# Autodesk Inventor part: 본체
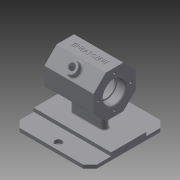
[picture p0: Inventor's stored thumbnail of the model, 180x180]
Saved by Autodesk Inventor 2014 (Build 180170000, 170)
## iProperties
Created: 2018-06
Part Number: 본체
Material: Generic
Document SubType Name: Modeling
Designer: kh
Density: 1 g/cm^3
Appearance: Default
Author: kh
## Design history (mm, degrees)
sketch "Sketch1"
  geometry: L1 (-55, -55)-(55, -55); L2 (55, -55)-(55, 55); L3 (55, 55)-(-55, 55); L4 (-55, 55)-(-55, -55); L5 (-55, -55)-(55, 55); L6 (55, -55)-(-55, 55); 1 further point
  constraints: 12 end point, 2 midpoint, 2 parallel, 1 horizontal, 1 perpendicular
  dimensions: "d0" = 110 distance of L3.end L2.end; "d1" = 110 distance of L3.end L1.start
extrude "Extrusion1" new body sketch "Sketch1" distance "d2" = 5; taper "d3" = 0 deg
chamfer "Chamfer1" distance "d4" = 10; stored, may be unused: second distance "d5" = 2, angle "d6" = 45 deg
sketch "Sketch2"
  geometry: L1 (-45, -55)-(-55, -45) reference; L2 (-45, -55)-(45, -55) reference; L3 (55, -45)-(45, -55) reference; L4 (55, -45)-(55, 45) reference; L5 (45, 55)-(55, 45) reference; L6 (45, 55)-(-45, 55) reference; L7 (-55, 45)-(-45, 55) reference; L8 (-55, 45)-(-55, -45) reference; L9 (-55, 25)-(55, 25); L10 (55, 25)-(55, -25); L11 (55, -25)-(-55, -25); L12 (-55, -25)-(-55, 25); L13 (0, 0)-(0, 55)
  constraints: 10 end point, 2 parallel, 2 point on line, 1 horizontal, 1 midpoint, 1 perpendicular
  dimensions: "d7" = 30 distance between parallel lines of L11 L2; "d8" = 30 distance between parallel lines of L9 L6
extrude "Extrusion2" join sketch "Sketch2" distance "d9" = 5; taper "d10" = 0 deg
workplane "Work Plane1"
sketch "Sketch3"
  geometry: L1 (35, 62)-(-35, 62); L2 (-35, 92)-(35, 92); L3 (-35, 92)-(-35, 62); L4 (35, 92)-(35, 62); 1 further point
  constraints: 8 end point, 2 parallel, 1 perpendicular
  dimensions: "d13" = 70 distance of L2.start L2.end
revolve "Revolution1" sketch "Sketch3" stored, may be unused: angle "d15" = 90 deg
sketch "Sketch4"
  geometry: L1 (-55, -45)-(-45, -55) reference; L2 (-55, 45)-(-55, -45) reference; L3 (-45, 55)-(-55, 45) reference; L4 (45, 55)-(-45, 55) reference; L5 (55, 45)-(45, 55) reference; L6 (55, -45)-(55, 45) reference; L7 (45, -55)-(55, -45) reference; L8 (-45, -55)-(45, -55) reference; L9 (55, -25)-(-55, -25) reference; L10 (-19, 0)-(19, 0); L11 (-19, -5)-(19, -5); L12 (19, 5)-(-19, 5); A1 r 5 centre (-19, 0) between (-19, 5) and (-19, -5); A2 r 5 centre (19, 0) between (19, -5) and (19, 5); 2 further points
  constraints: 8 end point, 4 point on circle, 4 tangent, 2 centre point, 2 parallel, 1 coincident, 1 midpoint
  dimensions: "d16" = 38 distance of L10.start L10.end; "d17" = 10 diameter of A2
extrude "Extrusion3" join sketch "Sketch4" stored distance "d18" = 5; taper "d19" = 0 deg
sketch "Sketch5"
  geometry: L1 (35, -30)-(35, 30) reference; L2 (55, -45)-(55, -25) reference; L3 (-45, -55)-(45, -55) reference; L4 (0, -55)-(0, -25); L5 (-13.688, -45)-(25.666, -45); 2 further points
  constraints: 4 end point, 2 perpendicular, 2 point on line, 1 midpoint
  dimensions: "d20" = 10 distance between parallel lines of L5 L3
hole "Hole1" sketch "Sketch5" at (0, -45) diameter "d21" = 10; stored, may be unused: countersink angle "d25" = 90 deg, drill point angle "d27" = 118 deg; dims "d22" = 6, "d23" = 4, "d24" = 2, "d26" = 8
mirror "Mirror1"
sketch "Sketch6"
  geometry: L1 (30, -12.426)-(12.426, -30); L2 (12.426, -30)-(-12.426, -30); L3 (-12.426, -30)-(-30, -12.426); L4 (-30, -12.426)-(-30, 12.426); L5 (-30, 12.426)-(-12.426, 30); L6 (-12.426, 30)-(12.426, 30); L7 (12.426, 30)-(30, 12.426); L8 (30, 12.426)-(30, -12.426); L9 (0, 0)-(30, 0); 2 further points
  constraints: 18 end point, 1 coincident, 1 horizontal alignment, 1 midpoint, 1 perpendicular, 18 other
extrude "Extrusion4" join sketch "Sketch6" distance "d28" = 70; taper "d29" = 0 deg
sketch "Sketch7"
  geometry: L1 (-35, 49.574)-(-35, 74.426) reference; L2 (35, 49.574)-(35, 74.426) reference; L3 (-35, 62)-(35, 62); L4 (-23, 78)-(-23, 76); L5 (-23, 76)-(-19.455, 76); L6 (-19.455, 76)-(-19.455, 87); L7 (-19.455, 87)-(20.545, 87); L8 (20.545, 87)-(20.545, 76); L9 (20.545, 76)-(23, 76); L10 (-23, 78)-(-35, 78); L11 (23, 76)-(23, 78); L12 (23, 78)-(35, 78); L13 (-35, 78)-(-35, 62); L14 (35, 78)-(35, 62); 1 further point
  constraints: 24 end point, 3 perpendicular, 2 collinear, 2 midpoint, 2 parallel, 1 point on line
  dimensions: "d30" = 32 diameter of L10 L3; "d31" = 28 diameter of L5 L3; "d32" = 50 diameter of L7 L3; "d33" = 28 diameter of L9 L3; "d34" = 32 diameter of L12 L3; "d35" = 12 distance between parallel lines of L4 L13; "d37" = 12 distance of L11.end L12.end; "d38" = 40 distance between parallel lines of L8 L6
revolve "Revolution2" sketch "Sketch7" stored, may be unused: angle "d39" = 90 deg
sketch "Sketch8" dims "d40" = 46
  geometry: L1 (42.426, 42.426)-(60, 24.853) reference; L2 (17.574, 42.426)-(42.426, 42.426) reference; L3 (0, 24.853)-(17.574, 42.426) reference; L4 (0, 0)-(0, 24.853) reference; L5 (17.574, -17.574)-(0, 0) reference; L6 (42.426, -17.574)-(17.574, -17.574) reference; L7 (60, 0)-(42.426, -17.574) reference; L8 (60, 24.853)-(60, 0) reference; L9 (30, 12.426)-(60, 12.426); C1 r 14 at (30, 12.426) reference; C2 r 16 at (30, 12.426) reference; 3 further points
  constraints: 2 end point, 1 coincident, 1 horizontal alignment, 1 midpoint, 2 other
hole "Hole2" sketch "Sketch8" at (53, 12.426) diameter "d41" = 3.459; stored, may be unused: countersink angle "d45" = 90 deg, drill point angle "d47" = 118 deg; dims "d42" = 8, "d43" = 4, "d44" = 2, "d46" = 10
pattern_circular "Circular Pattern1" dims angle "d49" = 360 deg
mirror "Mirror2"
sketch "Sketch9"
  geometry: L1 (10.113, 16.029)-(59.887, 16.029); L2 (59.887, 16.029)-(59.887, 8.824); L3 (59.887, 8.824)-(10.113, 8.824); L4 (10.113, 8.824)-(10.113, 16.029); L5 (10.113, 16.029)-(59.887, 8.824); L6 (10.113, 8.824)-(59.887, 16.029); 2 further points
  constraints: 4 end point, 1 coincident, 1 midpoint, 2 other
emboss "Emboss1" sketch "Sketch9" dims "d0" = 110, "d1" = 110, "d51" = 0.5, "d52" = 0
workplane "Work Plane2"
sketch "Sketch10"
  geometry: L1 (70, 0)-(70, -24.853) reference; L2 (0, 0)-(70, 0) reference; L3 (0, 0)-(0, -24.853) reference; L4 (0, -24.853)-(70, -24.853) reference; L5 (35, -4.656)-(35, -24.853); L6 (0, -12.426)-(58.315, -12.426); C1 r 8 at (35, -12.426); 2 further points
  constraints: 4 end point, 2 midpoint, 2 perpendicular, 2 point on line, 1 centre point, 1 coincident
  dimensions: "d54" = 35 distance between parallel lines of L5 L3; "d55" = 16 diameter of C1
extrude "Extrusion5" join sketch "Sketch10" stored distance "d56" = 0; taper "d57" = 0 deg
sketch "Sketch11"
  geometry: C1 r 8 at (0, 0) reference; C2 r 4 at (0, 0); 1 further point
  constraints: 1 centre point, 1 coincident
  dimensions: "d58" = 8 diameter of C2
extrude "Extrusion6" cut sketch "Sketch11" stored distance "d59" = 70; taper "d60" = 0 deg
fillet "Fillet1" dims "d61" = 3
fillet "Fillet2" dims "d62" = 2
fillet "Fillet3" dims "d63" = 1
chamfer "Chamfer2" distance "d64" = 1; stored, may be unused: second distance "d65" = 2, angle "d66" = 45 deg
chamfer "Chamfer3" distance "d67" = 1; stored, may be unused: second distance "d68" = 2, angle "d69" = 45 deg
fillet "Fillet4" dims "d70" = 3, "d71" = 0.3
body "Solid1"
node "Projected Loop1"
node "Projected Loop2"
node "Projected Loop3"
node "Projected Loop4"
node "Projected Loop5"
node "Projected Loop6"
other parameters: "d11" = 0, "d53" = 7
